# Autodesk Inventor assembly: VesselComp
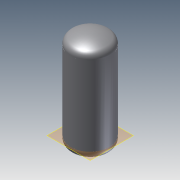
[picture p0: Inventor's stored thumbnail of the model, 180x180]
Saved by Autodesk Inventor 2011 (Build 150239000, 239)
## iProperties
Created: 2010-06
Part Number: VesselComp
Document SubType Name: Assembly
Designer: mklassen
OD: 36.000 in
THK: 0.625 in
LEN: 6.000 ft
Author: mklassen
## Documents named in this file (3)
- O:\cadd\tutorials\inventor 2011\iLogic\VesselComp.iam
- O:\cadd\tutorials\inventor 2011\iLogic\Shell-02.ipt
- O:\cadd\tutorials\inventor 2011\iLogic\Head-02.ipt
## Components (3 placed, 2 different names)
1. Shell-02:1 — Mate:2
2. Head-02:1
3. Head-02:2
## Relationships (1: Mate 1)
- Mate:2: Shell-02:1
## Named parameters: SKOFS = -152.4 mm
